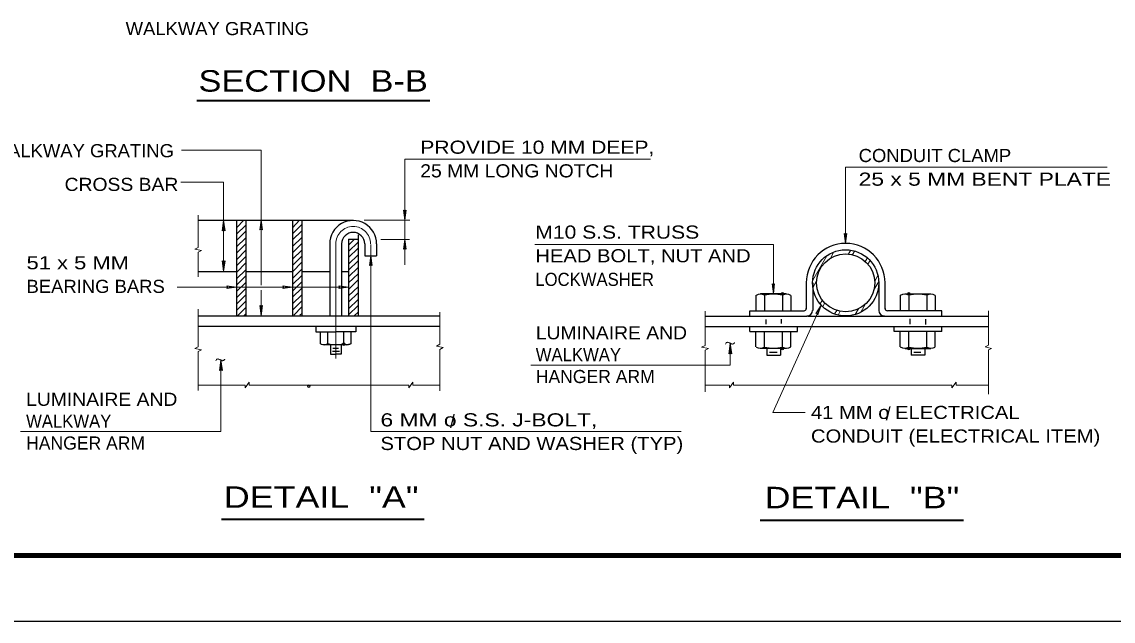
# Model space of a CAD drawing. Extents: x 312601.858 to 312602.699, y 144420.109 to 144420.704.
# Drawn here: x 312602.0138 to 312602.2633, y 144420.1095 to 144420.2464 of the extents above; entities that cross this region are included whole.
import ezdxf
from ezdxf.enums import TextEntityAlignment as Align

# ---------------------------------------------------------------- set-up
doc = ezdxf.new("R2010")
doc.units = 0
doc.header["$LTSCALE"] = 0.0012
doc.header["$PDMODE"] = 32
doc.header["$PDSIZE"] = 0.0006
doc.linetypes.add('DOT_DASHED', pattern=[7.7, 5, -1.2, 0.3, -1.2])
for name, color, linetype, lineweight in [('1', 7, 'Continuous', 13), ('2', 7, 'Continuous', 13), ('39', 7, 'Continuous', 13)]:
    doc.layers.add(name, color=color, linetype=linetype, lineweight=lineweight)

msp = doc.modelspace()

# ---------------------------------------------------------------- hatches: boundary and pattern name
at = {"layer": '39'}
for points in [[(312602.0599, 144420.1989), (312602.0596, 144420.1987), (312602.0599, 144420.2011), (312602.0603, 144420.1987)], [(312602.0599, 144420.1916), (312602.0603, 144420.1918), (312602.0599, 144420.1894), (312602.0596, 144420.1918)], [(312602.1757, 144420.1708), (312602.1754, 144420.1706), (312602.1757, 144420.173), (312602.1761, 144420.1706)], [(312602.1757, 144420.1708), (312602.1754, 144420.1706), (312602.1757, 144420.173), (312602.1761, 144420.1706)], [(312602.0593, 144420.167), (312602.059, 144420.1668), (312602.0593, 144420.1692), (312602.0597, 144420.1668)]]:
    msp.add_hatch(color=256, dxfattribs=at).paths.add_polyline_path(points)

# ---------------------------------------------------------------- linework, layer by layer
at = {"layer": '1'}
for p, q in [((312602.0685, 144420.2171), (312602.0503, 144420.2171)), ((312602.1575, 144420.2151), (312602.1014, 144420.2151)), ((312602.2021, 144420.2132), (312602.2021, 144420.1958)), ((312602.2021, 144420.2132), (312602.2619, 144420.2132)), ((312602.0502, 144420.2098), (312602.0599, 144420.2098)), ((312602.0541, 144420.2023), (312602.0541, 144420.1949)), ((312602.0629, 144420.1994), (312602.0646, 144420.2011)), ((312602.0757, 144420.1994), (312602.0773, 144420.2011)), ((312602.0921, 144420.2011), (312602.1025, 144420.2011)), ((312602.0629, 144420.1979), (312602.065, 144420.2)), ((312602.0629, 144420.1965), (312602.065, 144420.1986)), ((312602.0757, 144420.198), (312602.0778, 144420.2001)), ((312602.0757, 144420.1966), (312602.0778, 144420.1987)), ((312602.0629, 144420.195), (312602.065, 144420.1971)), ((312602.0757, 144420.1951), (312602.0778, 144420.1972)), ((312602.0885, 144420.1954), (312602.0899, 144420.1968)), ((312602.0885, 144420.194), (312602.0907, 144420.1961)), ((312602.0959, 144420.1967), (312602.1024, 144420.1967)), ((312602.1014, 144420.1967), (312602.1014, 144420.1909)), ((312602.0534, 144420.1945), (312602.0541, 144420.1949)), ((312602.0534, 144420.1945), (312602.0549, 144420.1942)), ((312602.0541, 144420.1938), (312602.0549, 144420.1942)), ((312602.0541, 144420.1938), (312602.0541, 144420.1882)), ((312602.0629, 144420.1936), (312602.065, 144420.1957)), ((312602.0629, 144420.1921), (312602.065, 144420.1943)), ((312602.0757, 144420.1937), (312602.0778, 144420.1958)), ((312602.0757, 144420.1922), (312602.0778, 144420.1943)), ((312602.0885, 144420.1926), (312602.0907, 144420.1947)), ((312602.1311, 144420.1956), (312602.1856, 144420.1956)), ((312602.1856, 144420.1956), (312602.1856, 144420.1843)), ((312602.1986, 144420.1923), (312602.1994, 144420.1939)), ((312602.2028, 144420.1934), (312602.2033, 144420.1943)), ((312602.2037, 144420.1933), (312602.2042, 144420.1941)), ((312602.0629, 144420.1907), (312602.065, 144420.1928)), ((312602.0629, 144420.1892), (312602.065, 144420.1914)), ((312602.0757, 144420.1908), (312602.0778, 144420.1929)), ((312602.0757, 144420.1893), (312602.0778, 144420.1915)), ((312602.0885, 144420.1911), (312602.0907, 144420.1932)), ((312602.0885, 144420.1897), (312602.0907, 144420.1918)), ((312602.0936, 144420.193), (312602.0936, 144420.1528)), ((312602.1946, 144420.1874), (312602.1978, 144420.193)), ((312602.2066, 144420.1917), (312602.2071, 144420.1925)), ((312602.2072, 144420.1911), (312602.2077, 144420.1919)), ((312602.0629, 144420.1877), (312602.065, 144420.1898)), ((312602.0757, 144420.1878), (312602.0778, 144420.1899)), ((312602.0885, 144420.1882), (312602.0907, 144420.1903)), ((312602.0885, 144420.1868), (312602.0907, 144420.1889)), ((312602.0629, 144420.1863), (312602.065, 144420.1884)), ((312602.0629, 144420.1848), (312602.065, 144420.1869)), ((312602.0757, 144420.1864), (312602.0778, 144420.1885)), ((312602.0757, 144420.1849), (312602.0778, 144420.187)), ((312602.0885, 144420.1853), (312602.0907, 144420.1875)), ((312602.1931, 144420.1868), (312602.1931, 144420.186)), ((312602.1947, 144420.1858), (312602.1955, 144420.1873)), ((312602.2086, 144420.1852), (312602.2097, 144420.1871)), ((312602.2088, 144420.1872), (312602.2095, 144420.1885)), ((312602.2111, 144420.1868), (312602.2111, 144420.186)), ((312602.0493, 144420.1858), (312602.0629, 144420.1858)), ((312602.0629, 144420.1834), (312602.065, 144420.1855)), ((312602.0629, 144420.1819), (312602.065, 144420.1841)), ((312602.0685, 144420.1851), (312602.0685, 144420.1793)), ((312602.0757, 144420.1858), (312602.0885, 144420.1858)), ((312602.0757, 144420.1835), (312602.0778, 144420.1856)), ((312602.0757, 144420.182), (312602.0778, 144420.1841)), ((312602.0885, 144420.1838), (312602.0907, 144420.1859)), ((312602.0885, 144420.1824), (312602.0907, 144420.1845)), ((312602.0629, 144420.1805), (312602.065, 144420.1826)), ((312602.0631, 144420.1793), (312602.065, 144420.1812)), ((312602.0757, 144420.1806), (312602.0778, 144420.1827)), ((312602.076, 144420.1794), (312602.0778, 144420.1813)), ((312602.0885, 144420.1809), (312602.0907, 144420.183)), ((312602.0885, 144420.1795), (312602.0907, 144420.1816)), ((312602.1965, 144420.1817), (312602.1855, 144420.1572)), ((312602.1963, 144420.182), (312602.1968, 144420.1829)), ((312602.1969, 144420.1814), (312602.1974, 144420.1822)), ((312602.2056, 144420.1801), (312602.2067, 144420.182)), ((312602.0541, 144420.1808), (312602.0541, 144420.1722)), ((312602.0646, 144420.1793), (312602.065, 144420.1797)), ((312602.0774, 144420.1794), (312602.0778, 144420.1798)), ((312602.0898, 144420.1793), (312602.0907, 144420.1801)), ((312602.1094, 144420.1801), (312602.1094, 144420.1728)), ((312602.17, 144420.1803), (312602.17, 144420.1725)), ((312602.1816, 144420.1804), (312602.1856, 144420.1804)), ((312602.1896, 144420.1804), (312602.1875, 144420.1804)), ((312602.1996, 144420.1797), (312602.2001, 144420.1805)), ((312602.2004, 144420.1794), (312602.2009, 144420.1803)), ((312602.2043, 144420.1796), (312602.2051, 144420.1809)), ((312602.2101, 144420.1792), (312602.2088, 144420.1792)), ((312602.2169, 144420.1792), (312602.211, 144420.1792)), ((312602.2146, 144420.1804), (312602.2186, 144420.1804)), ((312602.2204, 144420.1792), (312602.2168, 144420.1792)), ((312602.2226, 144420.1804), (312602.2186, 144420.1804)), ((312602.2348, 144420.1804), (312602.2348, 144420.1726)), ((312602.0821, 144420.1756), (312602.0856, 144420.1756)), ((312602.0891, 144420.1756), (312602.0856, 144420.1756)), ((312602.1816, 144420.1757), (312602.1856, 144420.1757)), ((312602.1896, 144420.1757), (312602.1856, 144420.1757)), ((312602.2146, 144420.1757), (312602.2186, 144420.1757)), ((312602.2226, 144420.1757), (312602.2186, 144420.1757)), ((312602.0534, 144420.1718), (312602.0541, 144420.1722)), ((312602.0534, 144420.1718), (312602.0549, 144420.1715)), ((312602.0541, 144420.1711), (312602.0549, 144420.1715)), ((312602.0541, 144420.1711), (312602.0541, 144420.1622)), ((312602.1086, 144420.1723), (312602.1094, 144420.1728)), ((312602.1086, 144420.1723), (312602.1101, 144420.172)), ((312602.1094, 144420.1716), (312602.1101, 144420.172)), ((312602.1094, 144420.1716), (312602.1094, 144420.1621)), ((312602.1692, 144420.1721), (312602.17, 144420.1725)), ((312602.1692, 144420.1721), (312602.1708, 144420.1718)), ((312602.17, 144420.1714), (312602.1708, 144420.1718)), ((312602.17, 144420.1714), (312602.17, 144420.1619)), ((312602.1757, 144420.173), (312602.1757, 144420.168)), ((312602.234, 144420.1722), (312602.2348, 144420.1726)), ((312602.234, 144420.1722), (312602.2355, 144420.1718)), ((312602.2348, 144420.1715), (312602.2355, 144420.1718)), ((312602.2348, 144420.1715), (312602.2348, 144420.1614)), ((312602.0593, 144420.1692), (312602.0593, 144420.1528)), ((312602.1302, 144420.168), (312602.1757, 144420.168)), ((312602.0649, 144420.1628), (312602.0658, 144420.1641)), ((312602.0658, 144420.1634), (312602.0658, 144420.1641)), ((312602.1023, 144420.1628), (312602.1032, 144420.1641)), ((312602.1032, 144420.1634), (312602.1032, 144420.1641)), ((312602.1756, 144420.1628), (312602.1765, 144420.1641)), ((312602.1765, 144420.1634), (312602.1765, 144420.1641)), ((312602.2264, 144420.1628), (312602.2274, 144420.1641)), ((312602.2274, 144420.1634), (312602.2274, 144420.1641)), ((312602.0541, 144420.1634), (312602.0649, 144420.1634)), ((312602.0649, 144420.1628), (312602.0649, 144420.1634)), ((312602.0658, 144420.1634), (312602.1023, 144420.1634)), ((312602.1023, 144420.1628), (312602.1023, 144420.1634)), ((312602.1032, 144420.1634), (312602.1094, 144420.1634)), ((312602.17, 144420.1634), (312602.1756, 144420.1634)), ((312602.1756, 144420.1628), (312602.1756, 144420.1634)), ((312602.1765, 144420.1634), (312602.2264, 144420.1634)), ((312602.2264, 144420.1628), (312602.2264, 144420.1634)), ((312602.2274, 144420.1634), (312602.2348, 144420.1634)), ((312602.1929, 144420.1572), (312602.1855, 144420.1572)), ((312602.0593, 144420.1528), (312602.0135, 144420.1528)), ((312602.1645, 144420.1528), (312602.0936, 144420.1528))]:
    msp.add_line(p, q, dxfattribs=at)
at = {"layer": '1', "lineweight": 25}
for p, q in [((312602.0541, 144420.2011), (312602.0896, 144420.2011)), ((312602.0629, 144420.2011), (312602.0629, 144420.1793)), ((312602.065, 144420.2011), (312602.065, 144420.1793)), ((312602.0757, 144420.2011), (312602.0757, 144420.1794)), ((312602.0778, 144420.2011), (312602.0778, 144420.1794)), ((312602.0885, 144420.1968), (312602.0907, 144420.1968)), ((312602.0885, 144420.1968), (312602.0885, 144420.1793)), ((312602.0907, 144420.1978), (312602.0907, 144420.1793)), ((312602.0842, 144420.1957), (312602.0842, 144420.1793)), ((312602.0869, 144420.1957), (312602.0869, 144420.1793)), ((312602.0922, 144420.1957), (312602.0922, 144420.193)), ((312602.0949, 144420.1957), (312602.0949, 144420.193)), ((312602.0922, 144420.193), (312602.0949, 144420.193)), ((312602.0541, 144420.1894), (312602.0629, 144420.1894)), ((312602.065, 144420.1894), (312602.0757, 144420.1894)), ((312602.0778, 144420.1894), (312602.0842, 144420.1894)), ((312602.0869, 144420.1894), (312602.0885, 144420.1894)), ((312602.1931, 144420.1867), (312602.1931, 144420.1809)), ((312602.1946, 144420.1868), (312602.1946, 144420.1805)), ((312602.2097, 144420.1868), (312602.2097, 144420.1805)), ((312602.2111, 144420.1868), (312602.2111, 144420.1809)), ((312602.1816, 144420.184), (312602.1816, 144420.1804)), ((312602.1885, 144420.1843), (312602.1827, 144420.1843)), ((312602.1836, 144420.184), (312602.1836, 144420.1804)), ((312602.1877, 144420.184), (312602.1877, 144420.1804)), ((312602.1896, 144420.1839), (312602.1896, 144420.1804)), ((312602.2146, 144420.184), (312602.2146, 144420.1804)), ((312602.2157, 144420.1843), (312602.2216, 144420.1843)), ((312602.2166, 144420.184), (312602.2166, 144420.1804)), ((312602.2207, 144420.184), (312602.2207, 144420.1804)), ((312602.2226, 144420.1839), (312602.2226, 144420.1804)), ((312602.0541, 144420.1793), (312602.1094, 144420.1793)), ((312602.17, 144420.1792), (312602.1841, 144420.1792)), ((312602.1802, 144420.1792), (312602.1802, 144420.1804)), ((312602.1802, 144420.1804), (312602.1926, 144420.1804)), ((312602.1839, 144420.1792), (312602.1874, 144420.1792)), ((312602.1873, 144420.1792), (312602.1933, 144420.1792)), ((312602.1935, 144420.1792), (312602.2348, 144420.1792)), ((312602.2241, 144420.1804), (312602.2117, 144420.1804)), ((312602.2168, 144420.1786), (312602.2168, 144420.1774)), ((312602.2241, 144420.1792), (312602.2241, 144420.1804)), ((312602.0541, 144420.1769), (312602.1094, 144420.1769)), ((312602.081, 144420.1769), (312602.081, 144420.1756)), ((312602.0902, 144420.1769), (312602.0902, 144420.1756)), ((312602.17, 144420.1768), (312602.2348, 144420.1768)), ((312602.1802, 144420.1757), (312602.1802, 144420.1768)), ((312602.1839, 144420.1784), (312602.1839, 144420.1774)), ((312602.1874, 144420.1785), (312602.1874, 144420.1775)), ((312602.1911, 144420.1757), (312602.1911, 144420.1768)), ((312602.2132, 144420.1757), (312602.2132, 144420.1768)), ((312602.2204, 144420.1785), (312602.2204, 144420.1773)), ((312602.2241, 144420.1757), (312602.2241, 144420.1768)), ((312602.081, 144420.1756), (312602.0856, 144420.1756)), ((312602.0821, 144420.1729), (312602.0821, 144420.1756)), ((312602.0838, 144420.1729), (312602.0838, 144420.1756)), ((312602.0902, 144420.1756), (312602.0856, 144420.1756)), ((312602.0874, 144420.1729), (312602.0874, 144420.1756)), ((312602.0891, 144420.1729), (312602.0891, 144420.1756)), ((312602.1802, 144420.1757), (312602.1911, 144420.1757)), ((312602.1816, 144420.1722), (312602.1816, 144420.1757)), ((312602.1836, 144420.1721), (312602.1836, 144420.1757)), ((312602.1877, 144420.1721), (312602.1877, 144420.1757)), ((312602.1896, 144420.1722), (312602.1896, 144420.1757)), ((312602.2241, 144420.1757), (312602.2132, 144420.1757)), ((312602.2146, 144420.1722), (312602.2146, 144420.1757)), ((312602.2166, 144420.1721), (312602.2166, 144420.1757)), ((312602.2207, 144420.1721), (312602.2207, 144420.1757)), ((312602.2226, 144420.1722), (312602.2226, 144420.1757)), ((312602.0821, 144420.1729), (312602.0826, 144420.1727)), ((312602.0826, 144420.1727), (312602.0885, 144420.1727)), ((312602.0844, 144420.1727), (312602.0844, 144420.1705)), ((312602.0848, 144420.1712), (312602.0864, 144420.1712)), ((312602.0849, 144420.1719), (312602.0862, 144420.1719)), ((312602.0891, 144420.1729), (312602.0885, 144420.1727)), ((312602.1885, 144420.1718), (312602.1827, 144420.1718)), ((312602.1841, 144420.1718), (312602.1841, 144420.1703)), ((312602.1872, 144420.1718), (312602.1872, 144420.1703)), ((312602.2157, 144420.1718), (312602.2216, 144420.1718)), ((312602.2171, 144420.1718), (312602.2171, 144420.1703)), ((312602.2202, 144420.1718), (312602.2202, 144420.1703)), ((312602.0844, 144420.1705), (312602.0856, 144420.1705)), ((312602.1841, 144420.1703), (312602.1872, 144420.1703)), ((312602.1847, 144420.171), (312602.1865, 144420.171)), ((312602.2202, 144420.1703), (312602.2171, 144420.1703)), ((312602.2177, 144420.171), (312602.2193, 144420.171))]:
    msp.add_line(p, q, dxfattribs=at)
at = {"layer": '1', "linetype": 'DOT_DASHED'}
for p, q in [((312602.0856, 144420.1695), (312602.0856, 144420.1957)), ((312602.0936, 144420.193), (312602.0936, 144420.1956))]:
    msp.add_line(p, q, dxfattribs=at)
at = {"layer": '1'}
for points in [[(312602.0685, 144420.2171), (312602.0685, 144420.2011), (312602.0685, 144420.1863)], [(312602.1014, 144420.2151), (312602.1014, 144420.2011), (312602.1014, 144420.1967)], [(312602.0599, 144420.2098), (312602.0599, 144420.2011), (312602.0599, 144420.1894)], [(312602.0629, 144420.1858), (312602.0689, 144420.1858), (312602.0757, 144420.1858)]]:
    msp.add_lwpolyline(points, dxfattribs=at)
for points in [[(312602.0682, 144420.1989), (312602.0685, 144420.2011), (312602.0688, 144420.1989), (312602.0685, 144420.1991)], [(312602.1017, 144420.2034), (312602.1014, 144420.2011), (312602.1011, 144420.2034), (312602.1014, 144420.2031)], [(312602.1011, 144420.1945), (312602.1014, 144420.1967), (312602.1017, 144420.1945), (312602.1014, 144420.1947)], [(312602.2024, 144420.1981), (312602.2021, 144420.1958), (312602.2018, 144420.1981), (312602.2021, 144420.1978)], [(312602.0933, 144420.1908), (312602.0936, 144420.193), (312602.0939, 144420.1908), (312602.0936, 144420.191)], [(312602.0607, 144420.1861), (312602.0629, 144420.1858), (312602.0607, 144420.1855), (312602.0609, 144420.1858)], [(312602.0735, 144420.1861), (312602.0757, 144420.1858), (312602.0735, 144420.1855), (312602.0737, 144420.1858)], [(312602.0863, 144420.1861), (312602.0885, 144420.1858), (312602.0863, 144420.1855), (312602.0865, 144420.1858)], [(312602.1859, 144420.1866), (312602.1856, 144420.1843), (312602.1853, 144420.1866), (312602.1856, 144420.1863)], [(312602.0688, 144420.1816), (312602.0685, 144420.1793), (312602.0682, 144420.1816), (312602.0685, 144420.1813)], [(312602.1953, 144420.1798), (312602.1965, 144420.1817), (312602.1958, 144420.1795), (312602.1957, 144420.1799)]]:
    msp.add_lwpolyline(points, close=True, dxfattribs=at)
at = {"layer": '1', "lineweight": 25}
msp.add_lwpolyline([(312602.0868, 144420.1727), (312602.0868, 144420.1705), (312602.0856, 144420.1705)], dxfattribs=at)
for radius in [0.007565, 0.00663]:
    msp.add_circle((312602.20213, 144420.1868), radius, dxfattribs=at)
for centre, radius, start, end in [((312602.08956, 144420.1957), 0.005356, 359.80523, 180.00052), ((312602.08956, 144420.1957), 0.002635, 0.19402, 180), ((312602.20213, 144420.1868), 0.00901, 0, 180), ((312602.19261, 144420.180935), 0.00051, 270, 0), ((312602.19329, 144420.18051), 0.001275, 270, 0), ((312602.21097, 144420.18051), 0.001275, 180, 270), ((312602.21165, 144420.180935), 0.00051, 180, 270), ((312602.08293, 144420.17411), 0.001445, 242.51946, 305.4373), ((312602.085565, 144420.17904), 0.006375, 253.73979, 286.2602), ((312602.0882, 144420.17411), 0.001445, 234.5627, 297.48054)]:
    msp.add_arc(centre, radius, start, end, dxfattribs=at)
at = {"layer": '1', "linetype": 'DOT_DASHED'}
msp.add_arc((312602.08956, 144420.1957), 0.003995, 0.06601, 180, dxfattribs=at)
at = {"layer": '1', "lineweight": 25}
for centre, major_axis, start_param, end_param in [((312602.182638, 144420.182775), (0.001722, 0), 0.970898, 2.1858445), ((312602.185632, 144420.178399), (0.006971, 0), 1.2763403, 1.8649531), ((312602.188626, 144420.182775), (0.001722, 0), 0.9448732, 2.1695573), ((312602.215634, 144420.182775), (-0.001722, 0), 4.113628, 5.3383121), ((312602.218628, 144420.178399), (-0.006971, 0), 4.4182323, 5.006845), ((312602.221622, 144420.182775), (-0.001722, 0), 4.0973408, 5.3122873), ((312602.182638, 144420.173315), (0.001722, 0), 4.0973408, 5.3122873), ((312602.185632, 144420.177691), (0.006971, 0), 4.4182323, 5.006845), ((312602.188626, 144420.173315), (0.001722, 0), 4.113628, 5.3383121), ((312602.215634, 144420.173315), (-0.001722, 0), 0.9448732, 2.1695573), ((312602.218628, 144420.177691), (-0.006971, 0), 1.2763403, 1.8649531), ((312602.221622, 144420.173315), (-0.001722, 0), 0.970898, 2.1858445)]:
    msp.add_ellipse(centre, major_axis=major_axis, ratio=0.83375, start_param=start_param, end_param=end_param, dxfattribs=at)
at = {"layer": '1'}
for centre, major_axis, ratio, start_param, end_param in [((312602.185558, 144420.175973), (-0.009881, 0), 0.83375, 4.4986502, 4.498801), ((312602.191695, 144420.175973), (0.009881, 0), 0.83375, 1.7843843, 1.7845351), ((312602.212565, 144420.175973), (-0.009881, 0), 0.83375, 4.4986502, 4.5023266), ((312602.218702, 144420.175973), (0.009881, 0), 0.83375, 1.7843843, 1.7845351), ((312602.085519, 144420.17911), (-0.008631, 0), 0.74025, 1.7843843, 1.7845351), ((312602.090881, 144420.17911), (0.008631, 0), 0.74025, 4.4986502, 4.498801), ((312602.185558, 144420.180117), (-0.009881, 0), 0.83375, 1.7843843, 1.7845351)]:
    msp.add_ellipse(centre, major_axis=major_axis, ratio=ratio, start_param=start_param, end_param=end_param, dxfattribs=at)
for p in [(312602.1877, 144420.1843), (312602.2166, 144420.1843), (312602.0874, 144420.1728), (312602.1877, 144420.1718), (312602.2166, 144420.1718), (312602.0794, 144420.1632)]:
    msp.add_point(p, dxfattribs=at)
at = {"layer": '2', "lineweight": 40}
for p, q in [((312602.0538, 144420.2285), (312602.1071, 144420.2285)), ((312602.0595, 144420.1328), (312602.1058, 144420.1328)), ((312602.1826, 144420.1326), (312602.2291, 144420.1326))]:
    msp.add_line(p, q, dxfattribs=at)
at = {"layer": '2'}
for points in [[(312602.1747, 144420.1728), (312602.1748, 144420.1731), (312602.175, 144420.1732), (312602.1752, 144420.1732), (312602.1755, 144420.1731), (312602.1756, 144420.1731), (312602.1757, 144420.173), (312602.1758, 144420.173), (312602.1759, 144420.1729), (312602.1761, 144420.1729), (312602.1762, 144420.1728), (312602.1763, 144420.1728), (312602.1765, 144420.1729), (312602.1766, 144420.1729), (312602.1766, 144420.173), (312602.1767, 144420.1731), (312602.1767, 144420.1732)], [(312602.0582, 144420.169), (312602.0583, 144420.1693), (312602.0585, 144420.1694), (312602.0587, 144420.1694), (312602.059, 144420.1693), (312602.0591, 144420.1693), (312602.0592, 144420.1692), (312602.0593, 144420.1692), (312602.0594, 144420.1691), (312602.0596, 144420.1691), (312602.0597, 144420.169), (312602.0598, 144420.169), (312602.06, 144420.1691), (312602.0601, 144420.1691), (312602.0601, 144420.1692), (312602.0602, 144420.1693), (312602.0602, 144420.1694)]]:
    msp.add_spline(points, degree=3, dxfattribs=at)
at = {"layer": '39', "lineweight": 158}
msp.add_line((312601.9088, 144420.1245), (312602.6838, 144420.1245), dxfattribs=at)
at = {"layer": '39', "lineweight": 25}
msp.add_line((312601.8578, 144420.1095), (312602.6988, 144420.1095), dxfattribs=at)
at = {"layer": '39'}
for points in [[(312602.0599, 144420.1989), (312602.0596, 144420.1987), (312602.0599, 144420.2011), (312602.0603, 144420.1987)], [(312602.0599, 144420.1916), (312602.0603, 144420.1918), (312602.0599, 144420.1894), (312602.0596, 144420.1918)], [(312602.1757, 144420.1708), (312602.1754, 144420.1706), (312602.1757, 144420.173), (312602.1761, 144420.1706)], [(312602.1757, 144420.1708), (312602.1754, 144420.1706), (312602.1757, 144420.173), (312602.1761, 144420.1706)], [(312602.0593, 144420.167), (312602.059, 144420.1668), (312602.0593, 144420.1692), (312602.0597, 144420.1668)]]:
    msp.add_lwpolyline(points, close=True, dxfattribs=at)

# ---------------------------------------------------------------- texts
at = {"layer": '2', "width": 1.05}
msp.add_text('WALKWAY GRATING', height=0.003, dxfattribs=at).set_placement((312602.0585, 144420.2434), align=Align.CENTER)
at = {"layer": '2'}
for s, height, width, p in [('SECTION  B-B', 0.0049, 1.2, (312602.0542, 144420.2305)), ('WALKWAY GRATING', 0.003, 1.05, (312602.0067, 144420.2155)), ('PROVIDE 10 MM DEEP, ', 0.003, 1.2, (312602.1049, 144420.2163)), ('CONDUIT CLAMP', 0.003, 1.05, (312602.2051, 144420.2144)), ('25 MM LONG NOTCH', 0.003, 1.1, (312602.1049, 144420.2109)), ('25 x 5 MM BENT PLATE', 0.003, 1.3, (312602.2051, 144420.209)), ('CROSS BAR', 0.003, 1.1, (312602.0236, 144420.2078)), ('M10 S.S. TRUSS', 0.003, 1.2, (312602.1312, 144420.1969)), ('HEAD BOLT, NUT AND', 0.003, 1.15, (312602.1312, 144420.1915)), ('51 x 5 MM', 0.003, 1.25, (312602.0149, 144420.1899)), ('LOCKWASHER', 0.003, 0.95, (312602.1312, 144420.1861)), ('BEARING BARS', 0.003, 1.05, (312602.0149, 144420.1845)), ('LUMINAIRE AND', 0.003, 1.1, (312602.1313, 144420.1739)), ('WALKWAY', 0.003, 0.95, (312602.1313, 144420.1689)), ('LUMINAIRE AND', 0.003, 1.1, (312602.0148, 144420.1587)), ('41 MM o ELECTRICAL', 0.003, 1.15, (312602.1942, 144420.1557)), ('WALKWAY', 0.003, 0.95, (312602.0148, 144420.1537)), ('6 MM o S.S. J-BOLT,', 0.003, 1.3, (312602.0958, 144420.154)), ('STOP NUT AND WASHER (TYP)', 0.003, 1.15, (312602.0958, 144420.1486)), ('CONDUIT (ELECTRICAL ITEM)', 0.003, 1.15, (312602.1942, 144420.1503)), ('DETAIL  "A"', 0.0049, 1.25, (312602.06, 144420.1354)), ('DETAIL  "B"', 0.0049, 1.25, (312602.1836, 144420.1353))]:
    msp.add_text(s, height=height, dxfattribs=dict(at, width=width)).set_placement(p)
for p in [(312602.1313, 144420.1639), (312602.0148, 144420.1487)]:
    msp.add_text('HANGER ARM', height=0.003, dxfattribs=at).set_placement(p)
for p in [(312602.11225, 144420.1537), (312602.21185, 144420.1554)]:
    msp.add_text('/', height=0.003, dxfattribs=at).set_placement(p, align=Align.CENTER)

doc.saveas('drawing.dxf')
